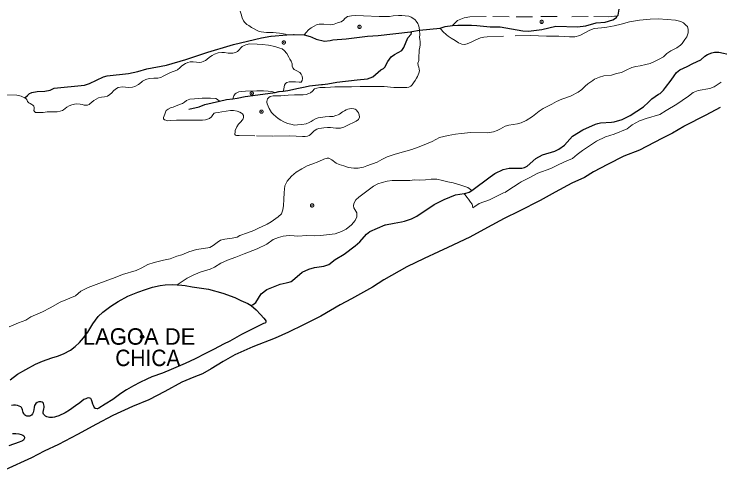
# Model space of a CAD drawing. Extents: x 267.7 to 296, y 7537.7 to 7565.8.
# Drawn here: x 272.267 to 276.556, y 7550.697 to 7553.465 of the extents above; entities that cross this region are included whole.
import ezdxf
from ezdxf.enums import TextEntityAlignment as Align

# ---------------------------------------------------------------- set-up
doc = ezdxf.new("R2010")
doc.units = 0
doc.header["$LTSCALE"] = 0.04
doc.header["$PDMODE"] = 32
doc.header["$PDSIZE"] = 0.02
doc.linetypes.add('SHORT_DASHED', pattern=[2.7, 1.5, -1.2])
for name, color, linetype, lineweight in [('2', 7, 'Continuous', 25), ('21', 7, 'SHORT_DASHED', 13), ('7', 7, 'Continuous', 25)]:
    doc.layers.add(name, color=color, linetype=linetype, lineweight=lineweight)
doc.layers.add('61', color=7, linetype='Continuous')

msp = doc.modelspace()

# ---------------------------------------------------------------- linework, layer by layer
at = {"layer": '2'}
for points in [[(276.5577, 7552.8982), (276.4719, 7552.851), (276.3389, 7552.7834), (276.3378, 7552.7824), (276.2691, 7552.7416), (276.2037, 7552.7094), (276.0674, 7552.6386), (275.972, 7552.6021), (275.8733, 7552.5506), (275.7874, 7552.5077), (275.7327, 7552.4734), (275.6565, 7552.439), (275.5546, 7552.3833), (275.4634, 7552.3318), (275.3357, 7552.2674), (275.2456, 7552.2234), (275.1437, 7552.1687), (275.0375, 7552.1097), (274.9034, 7552.0464), (274.8454, 7552.0217), (274.7585, 7551.9799), (274.6534, 7551.9294), (274.515, 7551.8511), (274.4453, 7551.8071), (274.3176, 7551.7363), (274.2489, 7551.6988), (274.1309, 7551.6312), (274.0258, 7551.5786), (273.9357, 7551.5325), (273.8541, 7551.4971), (273.7179, 7551.4434), (273.6084, 7551.3951)], [(272.2431, 7551.244), (272.2882, 7551.279), (272.338, 7551.3065), (272.3979, 7551.3383), (272.4388, 7551.3574), (272.4955, 7551.3781), (272.5299, 7551.3866), (272.567, 7551.4025), (272.6089, 7551.4247), (272.6386, 7551.4465), (272.6651, 7551.4709), (272.6895, 7551.4979), (272.7144, 7551.5324), (272.7446, 7551.5832), (272.7775, 7551.6278), (272.8061, 7551.6543), (272.8554, 7551.6909), (272.8994, 7551.7184), (272.9588, 7551.7523), (273.0182, 7551.7767), (273.0648, 7551.7921), (273.1077, 7551.8059), (273.1549, 7551.817), (273.1846, 7551.8207), (273.2281, 7551.8229), (273.2585, 7551.8207)], [(273.2585, 7551.8207), (273.2662, 7551.8202), (273.3065, 7551.8165), (273.3489, 7551.8091), (273.4481, 7551.7942), (273.5361, 7551.7709), (273.6087, 7551.7428), (273.6453, 7551.7258), (273.6882, 7551.7073), (273.7073, 7551.6956)], [(273.7073, 7551.6956), (273.7375, 7551.6691), (273.764, 7551.6405), (273.7852, 7551.6172), (273.7937, 7551.6082), (273.7969, 7551.6029), (273.7974, 7551.5944), (273.7958, 7551.5907), (273.7905, 7551.588), (273.7826, 7551.5853), (273.7663, 7551.5768), (273.7254, 7551.5564), (273.6492, 7551.5181), (273.5777, 7551.4787), (273.5398, 7551.4601), (273.4826, 7551.4292), (273.4307, 7551.4034), (273.3679, 7551.3703), (273.306, 7551.3432), (273.2212, 7551.3063), (273.168, 7551.284), (273.1048, 7551.2622), (273.0729, 7551.2471), (273.0305, 7551.227), (272.9931, 7551.2065), (272.9495, 7551.1824), (272.9149, 7551.1596), (272.8662, 7551.1244), (272.8215, 7551.0953), (272.7819, 7551.0715), (272.7731, 7551.0677), (272.7711, 7551.0675), (272.7646, 7551.0685), (272.7613, 7551.0695), (272.7573, 7551.0722), (272.7538, 7551.078), (272.7488, 7551.0886), (272.7455, 7551.0956), (272.7413, 7551.1104), (272.7383, 7551.1219), (272.7357, 7551.1269), (272.733, 7551.1297), (272.7277, 7551.1325), (272.7189, 7551.1335), (272.7114, 7551.1325), (272.7021, 7551.1292), (272.6916, 7551.1232), (272.6668, 7551.1044), (272.6412, 7551.0848), (272.6028, 7551.0585), (272.5772, 7551.0424), (272.5398, 7551.0251), (272.5195, 7551.0186), (272.5127, 7551.0171), (272.5007, 7551.015), (272.4829, 7551.0148), (272.4743, 7551.0163), (272.4661, 7551.0188), (272.4583, 7551.0233), (272.451, 7551.0293), (272.4465, 7551.0351), (272.4445, 7551.0409), (272.4447, 7551.0477), (272.4465, 7551.0574), (272.4487, 7551.067), (272.4492, 7551.0765), (272.4492, 7551.084), (272.4475, 7551.0926), (272.445, 7551.0996), (272.4427, 7551.1036), (272.4385, 7551.1079), (272.4304, 7551.1104), (272.4247, 7551.1109), (272.4166, 7551.1101), (272.4068, 7551.1059), (272.3998, 7551.1008), (272.3943, 7551.0946), (272.3905, 7551.0878), (272.3893, 7551.077), (272.387, 7551.0612), (272.3825, 7551.0454), (272.3795, 7551.0379), (272.373, 7551.0296), (272.3675, 7551.0251), (272.3602, 7551.0223), (272.3449, 7551.0226), (272.3368, 7551.0266), (272.3311, 7551.0311), (272.3253, 7551.0381), (272.3218, 7551.0459), (272.3198, 7551.0532), (272.318, 7551.0612), (272.3163, 7551.0682), (272.3123, 7551.0748), (272.3077, 7551.079)], [(273.6084, 7551.3951), (273.5376, 7551.3555), (273.4647, 7551.3104), (273.4121, 7551.2793), (273.3584, 7551.2589), (273.2855, 7551.2289)], [(273.2855, 7551.2289), (273.1825, 7551.172), (273.0849, 7551.1216), (272.9862, 7551.0819), (272.8671, 7551.0261), (272.7673, 7550.9735), (272.6525, 7550.9124), (272.5366, 7550.8512), (272.4497, 7550.8094), (272.3736, 7550.7707), (272.2126, 7550.6967)], [(272.3077, 7551.079), (272.298, 7551.0843), (272.2884, 7551.0873), (272.2759, 7551.0891), (272.2633, 7551.0896), (272.2503, 7551.0881)], [(272.2583, 7550.9171), (272.2774, 7550.9167), (272.2953, 7550.9155), (272.3108, 7550.9123), (272.3196, 7550.9083), (272.3268, 7550.9032), (272.33, 7550.8956), (272.33, 7550.8892), (272.3284, 7550.8849), (272.3236, 7550.8769), (272.3188, 7550.8733), (272.2985, 7550.865), (272.2352, 7550.8431)]]:
    msp.add_lwpolyline(points, dxfattribs=at)
msp.add_point((273.0447, 7551.505), dxfattribs=at)
at = {"layer": '21'}
for points in [[(273.6412, 7553.4835), (273.6478, 7553.4642), (273.6538, 7553.4428), (273.6619, 7553.4236), (273.6693, 7553.414), (273.6811, 7553.4014), (273.6944, 7553.3962), (273.71, 7553.3844), (273.7514, 7553.3615), (273.7691, 7553.3563), (273.8017, 7553.3533), (273.8165, 7553.3533), (273.8416, 7553.3526), (273.8593, 7553.3504), (273.8793, 7553.3489), (273.9045, 7553.3452), (273.9156, 7553.3422), (273.9254, 7553.3384)], [(274.0305, 7553.3395), (274.0413, 7553.3541), (274.0568, 7553.3696), (274.0731, 7553.3822), (274.0908, 7553.3918), (274.1049, 7553.3999), (274.1219, 7553.4036), (274.1485, 7553.4029), (274.1914, 7553.4006), (274.2128, 7553.4043), (274.2328, 7553.411), (274.255, 7553.4177), (274.2683, 7553.4288), (274.2772, 7553.4384), (274.2942, 7553.4495), (274.3179, 7553.4554), (274.3393, 7553.4561), (274.3896, 7553.4546), (274.4857, 7553.4509), (274.5146, 7553.4495), (274.5493, 7553.4509), (274.5708, 7553.4539), (274.6033, 7553.4561), (274.624, 7553.4561), (274.6433, 7553.4554), (274.6654, 7553.4524), (274.6802, 7553.4472), (274.6906, 7553.4406), (274.7039, 7553.4295), (274.7098, 7553.4228), (274.7202, 7553.4073), (274.7268, 7553.3925), (274.729, 7553.3807), (274.7319, 7553.3665)], [(274.9308, 7553.3963), (274.9626, 7553.426), (274.9817, 7553.4349), (275.0033, 7553.4425), (275.0363, 7553.4489), (275.1761, 7553.4502), (275.3184, 7553.4476), (275.4683, 7553.4502), (275.6564, 7553.4489), (275.7898, 7553.4502), (275.8787, 7553.4489), (275.9168, 7553.4514), (275.9331, 7553.4514)], [(274.857, 7553.38), (274.8736, 7553.3589), (274.8944, 7553.3381), (274.9061, 7553.3304), (274.9242, 7553.3187), (274.9476, 7553.3044), (274.9683, 7553.2914), (274.9891, 7553.2824), (275.0047, 7553.2811), (275.0215, 7553.2837), (275.0488, 7553.2966), (275.0734, 7553.3096), (275.1007, 7553.3213), (275.1214, 7553.3252), (275.1422, 7553.3278), (275.3121, 7553.333), (275.4055, 7553.3343), (275.5028, 7553.3304), (275.5768, 7553.3317), (275.6429, 7553.3278), (275.6753, 7553.3278), (275.7052, 7553.3343), (275.7402, 7553.3524), (275.7662, 7553.3667), (275.7934, 7553.3771), (275.8362, 7553.381), (275.8686, 7553.3848), (275.914, 7553.3939), (275.9556, 7553.4043), (276.0074, 7553.4173), (276.0684, 7553.429), (276.132, 7553.4341), (276.1813, 7553.4367), (276.2358, 7553.4328), (276.2864, 7553.4277), (276.3188, 7553.4199), (276.3357, 7553.4121), (276.3525, 7553.3965), (276.359, 7553.3887), (276.3642, 7553.3719), (276.3642, 7553.3511), (276.3564, 7553.3278), (276.3434, 7553.3109), (276.3266, 7553.2863), (276.3162, 7553.2759), (276.2941, 7553.2603), (276.2591, 7553.2421), (276.2345, 7553.2253), (276.2137, 7553.2058), (276.1865, 7553.1903), (276.1631, 7553.1799), (276.132, 7553.1656), (276.1073, 7553.1591), (276.0723, 7553.1513), (276.0464, 7553.1474), (276.0217, 7553.1397), (275.9867, 7553.1241), (275.9581, 7553.1098), (275.9283, 7553.1033), (275.8985, 7553.0943), (275.8518, 7553.0891), (275.8258, 7553.0826), (275.7947, 7553.0696), (275.7843, 7553.0618), (275.7532, 7553.0424), (275.7376, 7553.0281), (275.7169, 7553.0073), (275.6961, 7552.9905), (275.6494, 7552.9671), (275.5962, 7552.9477), (275.5638, 7552.9347), (275.5352, 7552.9178), (275.4833, 7552.8906), (275.4587, 7552.875), (275.4172, 7552.8439), (275.3783, 7552.8192), (275.3497, 7552.8037), (275.3264, 7552.7985), (275.2745, 7552.7907), (275.2511, 7552.7842), (275.2239, 7552.7686), (275.2031, 7552.7583), (275.1798, 7552.7492), (275.1435, 7552.744), (275.0436, 7552.7453), (274.9839, 7552.7401), (274.9489, 7552.7362), (274.9048, 7552.7284), (274.8529, 7552.7155), (274.8075, 7552.6908), (274.7595, 7552.67), (274.7219, 7552.6571), (274.6842, 7552.6428), (274.6116, 7552.6233), (274.5779, 7552.6117)], [(274.7319, 7553.3665), (274.7335, 7553.3393), (274.7305, 7553.3245), (274.7327, 7553.3097), (274.735, 7553.2979), (274.7357, 7553.2801), (274.732, 7553.2624), (274.729, 7553.2476), (274.729, 7553.2298), (274.7268, 7553.2143), (274.7268, 7553.201), (274.7276, 7553.1832), (274.7216, 7553.167), (274.7224, 7553.1529), (274.7268, 7553.1418), (274.7298, 7553.1307), (274.7305, 7553.1211), (274.7261, 7553.1063), (274.7231, 7553.0952), (274.7194, 7553.0856), (274.7128, 7553.0753), (274.7039, 7553.0619), (274.695, 7553.0479), (274.6854, 7553.0353), (274.6773, 7553.0279), (274.6654, 7553.022), (274.6543, 7553.0198), (274.6351, 7553.0183), (274.5752, 7553.0198), (274.5168, 7553.0242), (274.4236, 7553.025), (274.3704, 7553.0257), (274.3186, 7553.0227), (274.2165, 7553.0235), (274.1907, 7553.0205), (274.1574, 7553.019), (274.1426, 7553.0198), (274.1256, 7553.019), (274.1064, 7553.0161), (274.093, 7553.0102), (274.0812, 7552.9976), (274.0686, 7552.9865), (274.059, 7552.9821), (274.0413, 7552.9769), (274.0243, 7552.9747), (273.9984, 7552.9747), (273.9703, 7552.9747), (273.9326, 7552.9717), (273.8882, 7552.9688), (273.8653, 7552.9688), (273.8423, 7552.968), (273.8238, 7552.9636), (273.8157, 7552.9591), (273.8076, 7552.9495), (273.8024, 7552.9347), (273.8024, 7552.9296), (273.8046, 7552.9192), (273.8172, 7552.8911), (273.832, 7552.8682), (273.8438, 7552.8549), (273.8571, 7552.8438), (273.8727, 7552.8305), (273.8882, 7552.8201), (273.9059, 7552.8098), (273.9296, 7552.8001), (273.9481, 7552.7957), (273.971, 7552.7905), (273.9895, 7552.792), (274.0161, 7552.7942), (274.042, 7552.7979), (274.0605, 7552.8061), (274.0731, 7552.8127), (274.0856, 7552.8209), (274.1034, 7552.8312), (274.116, 7552.8356), (274.1574, 7552.8416), (274.184, 7552.8438), (274.2069, 7552.8438), (274.2217, 7552.8482), (274.2365, 7552.8527), (274.2446, 7552.8571), (274.2631, 7552.8704), (274.2742, 7552.8778), (274.2846, 7552.883), (274.2957, 7552.8874), (274.306, 7552.8896), (274.3179, 7552.8911), (274.3312, 7552.8904), (274.3393, 7552.8882), (274.3467, 7552.8837), (274.3548, 7552.8741), (274.3608, 7552.8645), (274.3644, 7552.8541), (274.3659, 7552.8393), (274.3622, 7552.829)], [(273.9026, 7552.9973), (273.9065, 7553.0086), (273.9079, 7553.0223), (273.9108, 7553.0331), (273.9173, 7553.0439), (273.9252, 7553.049), (273.9382, 7553.0526), (273.9592, 7553.054), (273.9772, 7553.054), (273.9988, 7553.0511), (274.0118, 7553.0518), (274.0183, 7553.062), (274.019, 7553.0728), (274.0176, 7553.0872), (274.0118, 7553.0995), (274.0039, 7553.1096), (273.9851, 7553.1197), (273.9693, 7553.1291), (273.9606, 7553.1377), (273.957, 7553.1478), (273.9563, 7553.1622), (273.9505, 7553.1788), (273.9433, 7553.1911), (273.9361, 7553.2034), (273.9238, 7553.2257), (273.9086, 7553.2445), (273.8971, 7553.2532), (273.8827, 7553.2589), (273.8516, 7553.2676), (273.8134, 7553.2763), (273.7752, 7553.2806), (273.7441, 7553.2828), (273.6972, 7553.2835), (273.6763, 7553.2777), (273.6655, 7553.2748), (273.6539, 7553.269), (273.6453, 7553.2604), (273.6345, 7553.2481), (273.6251, 7553.2387), (273.6128, 7553.2322), (273.5962, 7553.2279), (273.5673, 7553.2272), (273.5464, 7553.2308), (273.5305, 7553.2315), (273.5075, 7553.2294), (273.4851, 7553.2214), (273.4707, 7553.2142), (273.4555, 7553.2041), (273.4375, 7553.1889), (273.4295, 7553.1839), (273.4165, 7553.1774), (273.4057, 7553.1738), (273.392, 7553.1716), (273.3754, 7553.1731), (273.3545, 7553.1745), (273.3379, 7553.1745), (273.3235, 7553.1709), (273.309, 7553.1651), (273.2867, 7553.1507), (273.2737, 7553.1384), (273.26, 7553.1269), (273.2462, 7553.1211), (273.2347, 7553.1168), (273.2174, 7553.1096), (273.1734, 7553.0872), (273.1597, 7553.08), (273.1409, 7553.0757), (273.1156, 7553.0749), (273.0882, 7553.0728), (273.068, 7553.0677), (273.0478, 7553.0583), (273.0406, 7553.0511), (273.0233, 7553.0374), (273.0016, 7553.0252), (272.9872, 7553.0215), (272.9627, 7553.0194), (272.9446, 7553.0208), (272.9251, 7553.0223), (272.8999, 7553.0194), (272.8826, 7553.01), (272.8703, 7552.9985), (272.8602, 7552.9862), (272.8479, 7552.9761), (272.8342, 7552.9674), (272.8162, 7552.9631), (272.7982, 7552.9602), (272.7808, 7552.9566), (272.7664, 7552.9487), (272.752, 7552.94), (272.7397, 7552.9292), (272.7282, 7552.9198), (272.7224, 7552.9162), (272.7123, 7552.9119), (272.6928, 7552.9126), (272.6805, 7552.9155)], [(275.0021, 7552.3751), (275.0187, 7552.353), (275.0286, 7552.3405), (275.0412, 7552.3233), (275.0511, 7552.3101), (275.0537, 7552.2996), (275.0544, 7552.289), (275.0927, 7552.3144), (275.1557, 7552.3377), (275.2489, 7552.3823), (275.3012, 7552.4153), (275.3363, 7552.4382), (275.3488, 7552.4463), (275.4012, 7552.4725), (275.4497, 7552.4997), (275.5292, 7552.5278), (275.5787, 7552.5511), (275.6272, 7552.5734), (275.6602, 7552.588), (275.6883, 7552.6112), (275.7223, 7552.6374), (275.7649, 7552.6646), (275.8076, 7552.6937), (275.861, 7552.7189), (275.9143, 7552.7364), (275.9929, 7552.7674), (276.0239, 7552.7926), (276.0676, 7552.8169), (276.1093, 7552.8314), (276.1908, 7552.8557), (276.2296, 7552.879), (276.2956, 7552.9178), (276.3276, 7552.9401), (276.3654, 7552.9673), (276.3945, 7552.9886), (276.4246, 7553.0002), (276.4964, 7553.0138), (276.5226, 7553.0235), (276.5643, 7553.0516)], [(272.332, 7552.9559), (272.319, 7552.9624), (272.3096, 7552.966), (272.2829, 7552.9718), (272.2187, 7552.9754)], [(273.5964, 7552.9508), (273.6034, 7552.9681), (273.6114, 7552.9797), (273.6164, 7552.984), (273.633, 7552.9927), (273.6496, 7552.9956), (273.6727, 7552.997), (273.742, 7552.9992), (273.7715, 7552.9992), (273.7824, 7552.9985), (273.8105, 7552.9963), (273.8307, 7552.9941), (273.8528, 7552.988)], [(272.6026, 7552.9075), (272.5867, 7552.8989), (272.568, 7552.883), (272.5622, 7552.8794), (272.5478, 7552.8751), (272.5283, 7552.8722), (272.5189, 7552.8715), (272.4951, 7552.8715), (272.4677, 7552.8715), (272.4431, 7552.8671), (272.4265, 7552.8664), (272.4157, 7552.8664), (272.4071, 7552.8671), (272.3977, 7552.8678), (272.3912, 7552.8736), (272.3876, 7552.8801), (272.3883, 7552.8895), (272.3883, 7552.8982), (272.3861, 7552.9054), (272.3811, 7552.9126), (272.3739, 7552.9162), (272.3638, 7552.9212), (272.3558, 7552.927), (272.3486, 7552.935), (272.3457, 7552.9414), (272.3407, 7552.9494), (272.332, 7552.9559)], [(274.292, 7552.7876), (274.272, 7552.778), (274.2513, 7552.7728), (274.2217, 7552.7713), (274.1892, 7552.7757), (274.1722, 7552.7765), (274.1492, 7552.775), (274.1359, 7552.7728), (274.1197, 7552.7698), (274.1078, 7552.7654), (274.0916, 7552.7558), (274.079, 7552.7439), (274.0686, 7552.7328), (274.0605, 7552.7269), (274.0494, 7552.7232), (274.0354, 7552.7218), (274.0198, 7552.721), (273.9437, 7552.7247), (273.8401, 7552.7232), (273.7307, 7552.7247), (273.6345, 7552.7269), (273.619, 7552.7284), (273.6131, 7552.7299), (273.6094, 7552.7343), (273.6086, 7552.7395), (273.6101, 7552.7462), (273.6116, 7552.758), (273.6212, 7552.7794), (273.6308, 7552.7972), (273.6441, 7552.8105), (273.653, 7552.8209), (273.6589, 7552.8282), (273.6619, 7552.8371), (273.6604, 7552.8497), (273.6545, 7552.8586), (273.6486, 7552.863), (273.6382, 7552.8689), (273.6234, 7552.8748), (273.6012, 7552.8793), (273.582, 7552.8793), (273.5569, 7552.8748), (273.5303, 7552.8704), (273.5081, 7552.8682), (273.4911, 7552.8652), (273.4837, 7552.8623), (273.4748, 7552.8527), (273.4718, 7552.8467), (273.4667, 7552.8408), (273.4541, 7552.8312), (273.443, 7552.826), (273.4312, 7552.8223), (273.4127, 7552.8209), (273.3897, 7552.8209), (273.3616, 7552.8209), (273.3224, 7552.8216), (273.2544, 7552.8209), (273.216, 7552.8186), (273.2004, 7552.8172), (273.1893, 7552.8201), (273.1819, 7552.8231), (273.176, 7552.8297), (273.176, 7552.8379), (273.1834, 7552.8564), (273.1878, 7552.8697), (273.1915, 7552.8793), (273.2026, 7552.8882), (273.2211, 7552.897), (273.2337, 7552.9007), (273.2625, 7552.9118), (273.2899, 7552.9214), (273.3025, 7552.931), (273.3158, 7552.9407), (273.335, 7552.9473), (273.3631, 7552.951), (273.3883, 7552.9532), (273.4104, 7552.954), (273.4334, 7552.9547), (273.4615, 7552.9547), (273.4925, 7552.9518), (273.5036, 7552.9466), (273.5159, 7552.9366)], [(272.6805, 7552.9155), (272.6683, 7552.9176), (272.6488, 7552.9191), (272.6336, 7552.9176), (272.6178, 7552.914), (272.6026, 7552.9075)], [(274.3622, 7552.829), (274.36, 7552.8253), (274.3452, 7552.8149), (274.3253, 7552.8038), (274.3082, 7552.7957), (274.292, 7552.7876)], [(274.3897, 7552.5351), (274.3586, 7552.5286), (274.3327, 7552.5286), (274.3002, 7552.5338), (274.2717, 7552.5429), (274.2419, 7552.552), (274.2237, 7552.5598), (274.1978, 7552.5792), (274.1796, 7552.5896), (274.1705, 7552.5896), (274.1498, 7552.5844), (274.1186, 7552.5702), (274.0771, 7552.5533), (274.0473, 7552.5429), (274.0148, 7552.5248), (273.9811, 7552.504), (273.9526, 7552.4806), (273.9266, 7552.4508), (273.9124, 7552.421), (273.9085, 7552.3808), (273.9072, 7552.3392), (273.9046, 7552.3029), (273.8994, 7552.2757), (273.8929, 7552.2523), (273.8721, 7552.2329), (273.8293, 7552.203), (273.8047, 7552.1888), (273.7489, 7552.1628), (273.7242, 7552.1511), (273.6853, 7552.1369), (273.6399, 7552.12), (273.6218, 7552.1096), (273.5932, 7552.1044), (273.5478, 7552.098), (273.5219, 7552.0915), (273.5011, 7552.0785), (273.4778, 7552.059), (273.457, 7552.0474), (273.4181, 7552.0409), (273.3753, 7552.0357), (273.3299, 7552.0201), (273.2871, 7552.002), (273.2559, 7551.9942), (273.2157, 7551.9786), (273.1742, 7551.9695), (273.1184, 7551.9566), (273.0795, 7551.9449), (273.0432, 7551.9241), (273.0082, 7551.9086), (272.9264, 7551.8826), (272.881, 7551.8644), (272.8201, 7551.8437), (272.7824, 7551.8294), (272.7176, 7551.8048), (272.6722, 7551.7827), (272.6397, 7551.7529), (272.5463, 7551.7153), (272.4867, 7551.6815), (272.4387, 7551.6569), (272.3686, 7551.6257), (272.3375, 7551.605), (272.2947, 7551.5894), (272.2363, 7551.5648)], [(274.5779, 7552.6117), (274.535, 7552.5987), (274.5026, 7552.5818), (274.4741, 7552.5663), (274.4105, 7552.5429), (274.3897, 7552.5351)], [(273.5232, 7551.9514), (273.5634, 7551.9695), (273.614, 7551.9877), (273.6646, 7552.0097), (273.745, 7552.0383), (273.8021, 7552.0681), (273.841, 7552.0954), (273.8734, 7552.1083), (273.9033, 7552.1161), (273.9396, 7552.12), (273.9694, 7552.1187), (273.9915, 7552.1161), (274.046, 7552.12), (274.0914, 7552.1187), (274.129, 7552.12), (274.1653, 7552.1239), (274.2185, 7552.1304), (274.2574, 7552.1447), (274.286, 7552.1589), (274.3171, 7552.1849), (274.3392, 7552.2108), (274.3508, 7552.2342), (274.3495, 7552.2575), (274.3327, 7552.2874), (274.3301, 7552.3003), (274.3314, 7552.3146), (274.3443, 7552.3367), (274.3625, 7552.3535), (274.4105, 7552.3885), (274.4507, 7552.4197), (274.478, 7552.4339), (274.5039, 7552.443), (274.5337, 7552.4508), (274.5649, 7552.4534), (274.6414, 7552.4534), (274.6726, 7552.4534), (274.6998, 7552.4586), (274.7322, 7552.4573), (274.7673, 7552.4586), (274.8023, 7552.4625), (274.836, 7552.4625), (274.871, 7552.4534), (274.9035, 7552.4469), (274.9346, 7552.4391)], [(274.9346, 7552.4391), (274.9813, 7552.4262), (275.0254, 7552.4119), (275.0484, 7552.3945)], [(273.5232, 7551.9514), (273.4856, 7551.928), (273.4596, 7551.915), (273.3986, 7551.8969), (273.3545, 7551.88), (273.3182, 7551.8606), (273.2585, 7551.8207)]]:
    msp.add_lwpolyline(points, dxfattribs=at)
for p in [(274.3662, 7553.3875), (275.4734, 7553.4177), (273.9061, 7553.2925), (273.7113, 7552.9834), (273.7704, 7552.8723), (274.0782, 7552.3029)]:
    msp.add_point(p, dxfattribs=at)
at = {"layer": '7'}
for p, q in [((274.6852, 7553.3588), (274.7319, 7553.3665)), ((274.7319, 7553.3665), (274.857, 7553.38))]:
    msp.add_line(p, q, dxfattribs=at)
for points in [[(275.9331, 7553.4514), (275.9382, 7553.4584), (275.9383, 7553.4585), (275.9436, 7553.4954)], [(274.9308, 7553.3963), (274.964, 7553.3968), (275.0479, 7553.3979), (275.0799, 7553.395), (275.1611, 7553.3877), (275.2214, 7553.3875), (275.3589, 7553.3637), (275.3938, 7553.3621), (275.4738, 7553.3719), (275.5588, 7553.3911), (275.6907, 7553.3867), (275.7421, 7553.393), (275.8036, 7553.4111), (275.8592, 7553.4165), (275.9057, 7553.4293), (275.9278, 7553.4443), (275.9331, 7553.4514)], [(273.9026, 7552.9973), (273.93, 7553.0003), (273.9958, 7553.0158), (274.0354, 7553.024), (274.0631, 7553.0297), (274.135, 7553.0369), (274.1423, 7553.0377), (274.1741, 7553.0412), (274.2282, 7553.0523), (274.3511, 7553.0653), (274.4147, 7553.072), (274.4465, 7553.0836), (274.4959, 7553.127), (274.5125, 7553.1352), (274.5204, 7553.1432), (274.5384, 7553.177), (274.5597, 7553.2047), (274.5798, 7553.2199), (274.6231, 7553.2442), (274.6352, 7553.2629), (274.6609, 7553.3217), (274.6797, 7553.3431), (274.6852, 7553.3588)], [(274.0305, 7553.3395), (274.066, 7553.3298), (274.0773, 7553.3248), (274.1036, 7553.3132), (274.154, 7553.2998), (274.1873, 7553.3053), (274.2045, 7553.3082), (274.2844, 7553.3143), (274.302, 7553.3166), (274.4145, 7553.3316), (274.4797, 7553.3348), (274.6765, 7553.3574), (274.6852, 7553.3588)], [(274.857, 7553.38), (274.8863, 7553.3888), (274.9308, 7553.3963)], [(272.332, 7552.9559), (272.3475, 7552.9713), (272.3602, 7552.9825), (272.3715, 7552.9877), (272.3744, 7552.989), (272.4075, 7552.9944), (272.4529, 7552.996), (272.4855, 7553.0036), (272.5112, 7553.0145), (272.6943, 7553.0328), (272.7261, 7553.0428), (272.8103, 7553.084), (272.8333, 7553.0896), (272.9623, 7553.1039), (273.0184, 7553.1158), (273.0731, 7553.1324), (273.1923, 7553.1551), (273.3103, 7553.1889), (273.4436, 7553.2337), (273.5797, 7553.2744), (273.5995, 7553.2793), (273.7711, 7553.3217), (273.828, 7553.3308), (273.829, 7553.3309), (273.9254, 7553.3384)], [(273.9254, 7553.3384), (273.9645, 7553.3415), (273.9685, 7553.3414), (274.0305, 7553.3395)], [(275.0484, 7552.3945), (275.1608, 7552.476), (275.1882, 7552.4959), (275.2393, 7552.5209), (275.2752, 7552.5287), (275.3522, 7552.5297), (275.3698, 7552.5333), (275.3845, 7552.5416), (275.4376, 7552.5884), (275.4793, 7552.6097), (275.5537, 7552.6319), (275.5782, 7552.6443), (275.6117, 7552.6695), (275.6611, 7552.7226), (275.7241, 7552.7626), (275.7996, 7552.796), (275.8144, 7552.8), (275.8318, 7552.8047), (275.8969, 7552.8088), (275.914, 7552.8099), (275.9636, 7552.8256), (276.012, 7552.85), (276.0919, 7552.9012), (276.1232, 7552.9309), (276.1437, 7552.9504), (276.1842, 7552.9777), (276.1929, 7552.9836), (276.2135, 7553.002), (276.2268, 7553.0195), (276.26, 7553.0646), (276.2779, 7553.0891), (276.2925, 7553.1098), (276.3136, 7553.1257), (276.3572, 7553.1473), (276.3911, 7553.1641), (276.4403, 7553.1868), (276.4646, 7553.2103), (276.4814, 7553.2196), (276.5067, 7553.2302), (276.5229, 7553.2339), (276.5495, 7553.2345), (276.625, 7553.2179)], [(273.5964, 7552.9508), (273.6232, 7552.9539), (273.6723, 7552.964), (273.688, 7552.9673), (273.8528, 7552.988)], [(273.8528, 7552.988), (273.8753, 7552.9943), (273.877, 7552.9945), (273.9026, 7552.9973)], [(273.3294, 7552.8879), (273.392, 7552.9024), (273.4258, 7552.9154), (273.5159, 7552.9366)], [(273.5159, 7552.9366), (273.5573, 7552.9464), (273.5964, 7552.9508)], [(273.7073, 7551.6956), (273.72, 7551.7009), (273.7361, 7551.7132), (273.7692, 7551.7656), (273.8031, 7551.7932), (273.8841, 7551.8244), (273.9205, 7551.8319), (273.9443, 7551.8393), (273.9508, 7551.8413), (273.9598, 7551.846), (274.0181, 7551.8977), (274.0575, 7551.9167), (274.0918, 7551.9259), (274.1488, 7551.9334), (274.1791, 7551.9448), (274.2191, 7551.9746), (274.2738, 7552.0068), (274.3408, 7552.057), (274.368, 7552.0824), (274.409, 7552.1275), (274.4284, 7552.1443), (274.5229, 7552.1844), (274.5245, 7552.1847), (274.5774, 7552.1953), (274.6218, 7552.2032), (274.6393, 7552.2063), (274.6829, 7552.2219), (274.7146, 7552.2378), (274.8206, 7552.3089), (274.88, 7552.3385), (274.9504, 7552.3663), (275.0021, 7552.3751)], [(275.0021, 7552.3751), (275.0063, 7552.3758), (275.0333, 7552.3836), (275.0484, 7552.3945)]]:
    msp.add_lwpolyline(points, dxfattribs=at)

# ---------------------------------------------------------------- texts
at = {"layer": '61'}
msp.add_text('LAGOA DE', height=0.1, dxfattribs=at).set_placement((273.0268, 7551.4569), align=Align.CENTER)
at = {"layer": '61', "width": 0.95}
msp.add_text('   CHICA', height=0.1, dxfattribs=at).set_placement((273.0269, 7551.3269), align=Align.CENTER)

doc.saveas('drawing.dxf')
